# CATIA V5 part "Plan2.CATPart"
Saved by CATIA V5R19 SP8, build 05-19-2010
Part number: Plan2
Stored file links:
  U:\cfao\projet\Plan2.CATPart
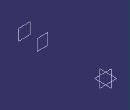
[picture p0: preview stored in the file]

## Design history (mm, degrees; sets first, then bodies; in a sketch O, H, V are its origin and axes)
Set1
  Plane1: type Offset, RefPlane zx-plane, Offset 630, reversed
  Plane2: type Offset, RefPlane zx-plane, Offset 810, reversed
Body1 (main body)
